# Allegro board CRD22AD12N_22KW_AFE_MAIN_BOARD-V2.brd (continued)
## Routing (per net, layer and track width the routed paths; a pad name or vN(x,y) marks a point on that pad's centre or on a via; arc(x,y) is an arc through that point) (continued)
GND_EARTH:
  vias: v1(48.26,79.38) v1(49.53,79.38) v1(49.53,58.42) v1(49.53,57.15) v1(49.53,55.88) v1(50.8,79.38) v1(68.58,46.99) v1(69.47,41.91) v1(69.47,40.64) v1(69.47,39.37) v1(69.85,46.99) v1(71.12,46.99) v1(83.13,69.85) v1(83.13,68.58) v1(83.13,67.31)
PGND: length 146.8
  TOP w0.762: v1(186.06,6.99) v1(184.78,6.99) 184.53,7.24 174.12,7.24 J2.5
  POWER03 w0.762: v1(271.78,15.24) v1(270.51,15.24) 227.08,15.24 222.63,10.79 220.09,10.79 216.85,7.56 214.95,7.56 211.84,4.45 188.59,4.45 v1(186.06,6.99)
  BOTTOM w0.381: R239.1 125.56,173.61 C23.2 ; C24.2 161.75,173.61 R227.1 ; R215.1 53.17,173.61 C27.2 ; R214.1 R236.1 197.95,173.61 C31.2 ; C28.2 91.44,172.13 92.92,173.61 R226.1
AC_LA: length 20.1
  BOTTOM w0.762: CL2_A1.6 128.91,72.53 R266.1 R28.1
AC_LA1: length 63.9
  POWER03 w2.54: RV2.1 186.32,30.86 213.74,30.86 222.53,39.65 RLY1.4
AC_LA_ADC: length 24.9
  TOP w0.152: v1(236.73,24.51) 239.9,21.34 239.9,4.7 J1.15
  BOTTOM w0.152: U4.12 v1(236.73,24.51)
AC_LA_OC: length 29.7
  TOP w0.152: v1(235.46,24.51) 235.46,10.16 J1.8
  BOTTOM w0.152: U4.13 v1(235.46,24.51) 235.71,24.51 237.87,22.35 237.87,20.09 237.21,19.43 R100.2
AC_LA_SAMP: length 117.2
  TOP w0.762: R146.1 52.83,11.56 v1(52.7,11.43)
  BOTTOM w0.762: v1(52.7,11.43) 54.48,13.21 82.17,13.21 83.52,14.55 83.52,20.14 86.74,23.37 113.16,23.37 116.59,26.8 116.59,36.96 111.38,42.16 111.38,52.58 R29.2
AC_LAB_G: length 30.1
  TOP w0.254: R155.1 R156.1 C171.2 57.53,20.32 57.66,20.19 C159.1 C160.1 60.83,20.19 61.09,20.45 67.31,20.45 C161.1 69.59,19.3 69.72,19.17 C164.1 C158.1 C157.1 74.42,20.45 76.46,20.45 D4.1 77.72,19.19 77.72,18.67 C166.2 78.74,17.66 U23.3
AC_LAB_SENSE: length 50
  TOP w0.254: D4.2 80.52,18.68 80.52,18.16 C166.1 v1(81.28,17.78) 81.28,17.53 80.01,16.25 U23.2 ; C167.1 C168.1 R153.2 50.67,17.14 50.67,16.51 R152.2 R146.2 50.67,12.7 50.67,12.19 v1(51.44,11.43)
  POWER03 w0.152: v1(81.28,17.78) 80.64,18.41 58.42,18.41 v1(51.44,11.43)
AC_LAB_SENSE_ADC: length 109.2
  POWER03 w0.152: v1(78.23,6.48) 79.06,5.65 83.12,5.65 84.58,7.11 107.19,7.11 111,3.3 159.38,3.3 161.29,1.4 175.9,1.4 J2.2
  BOTTOM w0.254: R154.2 C214.2 79.5,8.59 U24.1 78.93,8.57 78.23,7.87 v1(78.23,6.48)
AC_LB: length 38.8
  BOTTOM w0.762: CL2_A1.4 145.3,75.06 140.59,75.06 134.37,68.83 134.37,58.67 132.33,56.64 R37.1 R264.1
AC_LB_ADC: length 94.7
  TOP w0.152: J1.17 244.98,4.45 244.98,7.11 242.19,9.91 242.19,25.27 239.9,27.56 239.9,55.24 237.36,57.78 237.36,59.56 239.01,61.21 239.01,88.65 v1(236.73,90.93)
  BOTTOM w0.152: U5.12 v1(236.73,90.93)
AC_LB_OC: length 106
  TOP w0.152: v1(235.46,90.93) 237.87,88.52 237.87,61.34 234.44,57.91 234.44,51.18 236.98,48.64 236.98,27.43 234.44,24.89 234.44,11.05 230,6.6 230,5.08 230.63,4.45 232.28,4.45 J1.10
  BOTTOM w0.152: U5.13 v1(235.46,90.93) 236.47,89.92 236.73,89.92 237.87,88.77 237.87,86.51 237.21,85.85 R105.2
AC_LB_SAMP: length 81.9
  TOP w0.762: v1(88.27,11.43) 88.39,11.56 R163.1
  BOTTOM w0.762: R38.2 119.63,56.64 114.17,51.18 114.17,43.69 119.76,38.1 119.76,25.27 118.36,23.88 118.36,14.86 116.71,13.21 90.04,13.21 v1(88.27,11.43)
AC_LBC_G: length 29.7
  TOP w0.254: R175.1 R176.1 C193.2 94.1,20.32 C172.1 C173.1 102.75,20.32 C174.1 104.65,19.3 104.78,19.17 C177.1 C182.1 C181.1 109.6,20.7 111.77,20.7 D7.1 113.28,19.19 113.28,18.67 C180.2 114.3,17.66 U26.3
AC_LBC_SENSE: length 45
  TOP w0.254: C187.1 v1(85.72,19.05) ; C187.1 R170.2 85.85,16.76 85.85,16.13 R169.2 R163.2 ; C187.1 C186.1 ; D7.2 116.59,19.19 116.59,18.67 C180.1 115.69,16.64 v1(115.57,16.51) U26.2
  POWER03 w0.152: v1(115.57,16.51) 113.03,19.05 v1(85.72,19.05)
AC_LBC_SENSE_ADC: length 69.5
  POWER03 w0.152: v1(113.79,6.48) 116.46,3.81 159.6,3.81 161.6,1.8 173.76,1.8 J2.4
  BOTTOM w0.254: v1(113.79,6.48) 113.79,7.75 114.62,8.57 U27.1 115.06,8.59 C217.2 R164.2
AC_LC: length 28.8
  BOTTOM w0.762: CL2_A1.2 142.88,59.82 131.57,48.51 R45.1 R265.1
AC_LC1: length 94.7
  GND02 w2.54: RV5.1 176.93,19.94 202.31,19.94 204.85,22.48 204.85,40.89 218.31,54.36 218.31,63.86 RLY3.4
AC_LC_ADC: length 63.9
  TOP w0.152: J1.19 245.3,2.22 243.05,2.22 242.44,2.83 242.44,6.99 241.17,8.26 241.17,24.64 238.76,27.05 238.76,55.5 236.73,57.53 v1(236.73,57.91)
  BOTTOM w0.152: U6.12 v1(236.73,57.91)
AC_LC_OC: length 63.2
  TOP w0.152: J1.12 236.09,5.97 236.09,25.53 238,27.43 238,55.37 v1(235.46,57.91)
  BOTTOM w0.152: R108.2 237.21,52.83 237.87,53.49 237.87,55.75 236.73,56.9 236.47,56.9 v1(235.46,57.91) U6.13
AC_LC_SAMP: length 45.2
  TOP w0.762: v1(123.83,11.43) 123.95,11.56 R181.1
  BOTTOM w0.762: v1(123.83,11.43) 123.83,38.1 116.97,44.96 116.97,46.99 118.49,48.51 R46.2
AC_LCA_G: length 29.7
  TOP w0.254: R189.1 R190.1 C203.2 129.41,20.32 C198.1 C199.1 137.8,20.32 C190.1 139.57,19.3 139.7,19.17 C194.1 C189.1 C188.1 144.53,20.32 147.71,20.32 D10.1 148.84,19.19 148.84,18.67 C197.2 149.74,16.38 149.86,16.26 U30.3
AC_LCA_SENSE: length 45.8
  TOP w0.254: D10.2 152.27,19.31 152.27,18.8 C197.1 151.13,17.65 v1(151.13,16.51) U30.2 ; C202.1 v1(121.28,19.05) 121.16,18.92 R187.2 R181.2 ; C202.1 C201.1 ; C202.1 R188.2
  POWER03 w0.152: v1(151.13,16.51) 148.59,19.05 v1(121.28,19.05)
AC_LCA_SENSE_ADC: length 31.1
  POWER03 w0.152: v1(149.35,6.48) 151.51,4.32 159.81,4.32 161.9,2.22 171.64,2.22 J2.6
  BOTTOM w0.254: v1(149.35,6.48) 149.35,7.87 150.05,8.57 U31.1 150.6,9.89 C219.2 R179.2
CAN5V_GND: length 119.2
  POWER03 w0.152: J2.11 167.13,7.87 181.61,7.87 186.56,2.92 216.55,2.92 221.5,7.87 224.65,7.87 227.7,10.92 273.38,10.92 J5.2
CAN_5V: length 126.8
  POWER03 w0.152: J2.12 163.96,4.45 163.96,6.48 165.86,8.38 181.99,8.38 186.82,3.56 216.41,3.56 221.23,8.38 224.08,8.38 227.39,11.68 275.16,11.68 J5.1
CLAMPHA: length 17.4
  TOP w0.635: Q7.4 337.33,40 337.96,39.37 U17.7
  TOP w0.762: Q7.4 334.79,40.32 R69.2 332.49,43.81 R258.1
  BOTTOM w0.762: Q7.4 335.61,39.49 C7.1 R74.2
CLAMPHB: length 16.7
  TOP w0.635: U15.7 337.95,137.16 337.31,137.79 Q8.4
  TOP w0.762: R261.1 334.01,140.84 334.78,140.84 R70.2 334.79,138.11 Q8.4
  BOTTOM w0.762: Q8.4 335.61,137.28 C8.1 R75.2
CLAMPHC: length 16.7
  TOP w0.635: U19.7 337.96,88.27 337.33,88.9 Q9.4
  TOP w0.762: Q9.4 335.1,91.63 R71.2 334.78,91.95 R262.1
  BOTTOM w0.762: Q9.4 335.61,88.39 C9.1 R76.2
CLAMPLA: length 16.7
  TOP w0.635: U18.7 337.96,65.4 337.33,66.04 Q11.4
  TOP w0.762: R259.1 332.49,69.09 R86.2 334.79,66.36 Q11.4
  BOTTOM w0.762: Q11.4 335.61,65.53 C36.1 R91.2
CLAMPLB: length 16.7
  TOP w0.635: U16.7 338.2,163.19 337.57,163.83 Q10.4
  TOP w0.762: Q10.4 334.79,164.14 R82.2 332.49,166.88 R260.1
  BOTTOM w0.762: R87.2 C34.1 335.61,163.32 Q10.4
CLAMPLC: length 16.7
  TOP w0.635: Q12.4 337.69,114.93 338.33,114.3 U20.7
  TOP w0.762: R263.1 334.78,117.98 R85.2 334.79,115.25 Q12.4
  BOTTOM w0.762: R88.2 C35.1 335.61,114.42 Q12.4
GGND: length 309.8
  TOP w1.016: J4.6 301.68,2.74 302.39,2.03 309.37,2.03 318.77,11.43 347.85,11.43 360.28,23.86 U10.2
  GND02 w0.635: v1(215.26,10.29) 216.41,11.43 216.41,15.49 v1(215.26,16.64)
  POWER03 w0.508: J4.6 302.94,6.34 302.94,9.23 299.59,12.57 281.94,12.57 274.45,20.07 245.24,20.07 242.7,17.53 225.55,17.53 221.36,13.34 218.31,13.34 v1(215.26,10.29)
  BOTTOM w0.508: C2.1 R44.2 220.98,28.95 C1.2 ; C1.2 220.98,33.02 219.71,34.29 219.71,45.09 225.04,50.42 225.04,55.12 225.61,55.69 Q15.2 225.61,63.69 225.04,64.26 222.63,64.26 222.38,64.01 C213.2 ; C1.2 222.12,30.61 222.5,30.99 224.79,30.99 225.61,30.16 Q1.2 225.61,22.92 225.04,22.35 225.04,19.81 224.54,19.3 219.15,19.3 Q5.2 215.58,16.95 v1(215.26,16.64) 214.75,16.13 R66.1 212.6,16.13 212.09,16.64 U2.3 ; C213.2 220.98,66.17 220.09,67.06 220.09,80.52 225.17,85.6 225.17,89.28 225.61,89.72 Q4.2 225.61,96.59 224.92,97.28 221.23,97.28 C4.2 220.98,95.37 R62.2 C5.1 ; C213.2 220.85,63.88 R198.2 C212.1 ; Q2.2 215.58,10.6 v1(215.26,10.29) 214.75,9.78 R53.1 212.73,9.78 212.22,10.29 U1.3
  vias: v1(358.77,155.57) v1(358.77,153.03) v1(358.77,151.76) v1(358.77,129.54) v1(358.77,127) v1(358.77,125.73) v1(358.77,106.68) v1(358.77,104.14) v1(358.77,102.87) v1(358.77,80.64) v1(358.77,78.11) v1(358.77,76.83) v1(358.77,57.78) v1(358.77,55.24) v1(358.77,53.98) v1(358.77,31.75) v1(358.77,29.21) v1(358.77,27.94)
IOUT_ADC: length 344.6
  TOP w0.152: v1(19.05,97.79) 20.95,99.69 U3.12
  POWER03 w0.152: v1(153.67,2.54) 153.67,2.41 153.29,2.03 11.64,2.03 3.94,9.74 3.94,82.35 16.08,94.49 19.18,94.49 19.68,95 19.68,97.16 v1(19.05,97.79)
  BOTTOM w0.152: v1(153.67,2.54) 154.81,1.4 219.58,1.4 222,3.81 222,6.48 222.88,7.37 237.24,7.37 J1.14
LAB_G: length 13.3
  TOP w0.254: C171.1 R156.2 R155.2 55.12,16.89 55.51,16.5 D5.2 v1(54.15,15.88) R152.1 52.83,17.77 R153.1 C168.2 C167.2
  BOTTOM w0.152: R240.2 v1(54.15,15.88)
LBC_G: length 13.2
  TOP w0.254: C193.1 R176.2 R175.2 91.07,17.77 D9.2 v1(89.71,15.88) R169.1 88.39,17.77 R170.1 C187.2 C186.2
  BOTTOM w0.254: R241.2 v1(89.71,15.88)
LCA_G: length 13.8
  TOP w0.254: C201.2 C202.2 R188.1 123.95,17.77 R187.1 v1(125.27,15.88) D11.2 126.63,16.76 126.24,17.14 R189.2 R190.2 C203.1
  BOTTOM w0.254: R242.2 v1(125.27,15.88)
OUTPUT_OC: length 351
  TOP w0.152: R97.2 19.43,94.87 v1(19.05,95.25) 19.05,96.65 22.23,99.82 U3.13
  POWER03 w0.152: v1(19.05,95.25) 16.12,95.25 3.43,82.56 3.43,9.53 11.43,1.52 154.05,1.52 154.94,2.41 v1(154.94,2.54)
  BOTTOM w0.152: J1.16 239.14,8 222.63,8 221.49,6.86 221.49,4.32 219.07,1.91 155.57,1.91 v1(154.94,2.54)
PFC_G_HA: length 40.1
  TOP w0.762: Q7.3 337.96,37.46 339.87,35.56 C131.1 341.64,34.72 U10.6
  POWER03 w0.762: Q7.3 337.99,37.46 339.11,38.58 339.11,42.8 340.38,44.07 v1(342.78,44.07)
  BOTTOM w0.762: Q7.3 335.42,37.46 335.93,37.98 C7.2 R74.1 ; C130.2 342.91,44.19 v1(342.78,44.07)
PFC_G_HB: length 40.2
  TOP w0.762: U12.6 341.64,132.51 C117.1 339.24,133.35 337.33,135.25 Q8.3
  POWER03 w0.762: v1(342.78,141.86) 340.38,141.86 339.11,140.59 339.11,136.25 338.12,135.25 Q8.3
  BOTTOM w0.762: Q8.3 335.61,135.77 C8.2 R75.1 ; v1(342.78,141.86) 342.91,141.98 C116.2
PFC_G_HC: length 40.1
  TOP w0.762: Q9.3 337.95,86.36 339.85,84.45 C145.1 341.64,83.61 U14.6
  POWER03 w0.762: v1(342.78,92.96) 340.38,92.96 339.11,91.69 339.11,87.55 337.91,86.36 Q9.3
  BOTTOM w0.762: v1(342.78,92.96) 342.91,93.09 C144.2 ; R76.1 C9.2 335.61,86.87 Q9.3
PFC_G_LA: length 40.3
  TOP w0.762: Q11.3 337.33,63.5 339.24,61.59 C138.1 341.64,60.44 345.19,56.89 345.51,56.89 U9.6
  POWER03 w0.762: v1(342.78,70.1) 340.38,70.1 339.11,68.83 339.11,64.64 337.96,63.5 Q11.3
  BOTTOM w0.762: R91.1 C36.2 335.61,64.01 Q11.3 ; C137.2 342.91,70.23 v1(342.78,70.1)
PFC_G_LB: length 40.1
  TOP w0.762: U11.6 341.64,158.54 C124.1 339.24,159.38 337.33,161.29 Q10.3
  POWER03 w0.762: v1(342.78,167.89) 340.38,167.89 339.11,166.62 339.11,162.41 337.99,161.29 Q10.3
  BOTTOM w0.762: R87.1 C34.2 335.93,161.8 335.42,161.29 Q10.3 ; v1(342.78,167.89) 342.91,168.02 C123.2
PFC_G_LC: length 40.1
  TOP w0.762: U13.6 341.64,109.65 C152.1 340.12,110.49 338.22,112.39 Q12.3
  POWER03 w0.762: v1(342.78,119) 340.38,119 339.11,117.73 339.11,113.46 338.04,112.39 Q12.3
  BOTTOM w0.762: Q12.3 335.61,112.91 C35.2 R88.1 ; v1(342.78,119) 342.91,119.12 C151.2
PFCDRVHA: length 8.4
  TOP w0.635: U17.6 338.98,40.64 337.59,42.03 R69.1
  TOP w0.762: R69.1 338.84,45.07 D13.2
PFCDRVHB: length 7.8
  TOP w0.635: U15.6 338.71,138.43 337.59,139.55 R70.1
  TOP w0.762: D16.2 338.83,142.08 R70.1
PFCDRVHC: length 7.7
  TOP w0.635: R71.1 337.59,90.78 338.84,89.53 U19.6
  TOP w0.762: R71.1 338.95,93.32 D17.2
PFCDRVLA: length 7.9
  TOP w0.635: U18.6 338.58,66.67 337.59,67.67 R86.1
  TOP w0.762: R86.1 338.95,70.46 D14.2
PFCDRVLB: length 7.7
  TOP w0.635: U16.6 338.84,164.47 337.59,165.71 R82.1
  TOP w0.762: R82.1 338.95,168.25 D15.2
PFCDRVLC: length 7.8
  TOP w0.635: R85.1 337.59,116.69 338.71,115.57 U20.6
  TOP w0.762: R85.1 338.95,119.35 D18.2
PWM1A: length 165.3
  TOP w0.508: R126.1 v1(356.87,39.37)
  POWER03 w0.152: J1.1 225.41,1.41 231.66,1.41 232.56,2.31 232.56,3.99 233.12,4.55 257,4.55 259.22,2.32 339.38,2.32 356.46,19.41 356.46,38.96 v1(356.87,39.37)
PWM1B: length 191.3
  TOP w0.508: R130.1 v1(356.87,65.41)
  POWER03 w0.152: v1(356.87,65.41) 355.9,64.44 355.9,46.3 355.52,45.92 355.52,38.91 356.01,38.43 356.01,19.58 339.19,2.77 281.33,2.77 280.95,3.15 260.25,3.15 256.42,6.99 232.79,6.99 232.38,6.58 232.38,4.55 232.21,4.37 232.21,2.72 231.55,2.06 227.03,2.06 226.06,3.02 J1.3
PWM1C: length 262.4
  TOP w0.508: R118.1 v1(356.87,137.16)
  POWER03 w0.152: J1.5 227.33,4.57 227.33,6.86 228.98,8.51 257.05,8.51 260.88,4.67 280.95,4.67 281.94,3.68 338.58,3.68 354.74,19.84 354.74,32.74 352.98,34.49 352.98,46.05 354.81,47.88 354.81,59.94 354.33,60.43 354.33,70.15 354.79,70.61 354.79,82.73 354.33,83.19 354.33,95.12 355.6,96.39 355.6,135.89 v1(356.87,137.16)
PWM1D: length 286.1
  TOP w0.508: R122.1 v1(356.87,163.19)
  POWER03 w0.152: v1(356.87,163.19) 356.08,162.41 356.08,139.22 357.38,137.92 357.38,136.14 356.11,134.87 356.11,95.73 355.5,95.12 355.5,47.04 354.38,45.92 354.38,38.99 355.6,37.77 355.6,19.94 338.84,3.18 281.68,3.18 280.95,3.91 260.57,3.91 256.73,7.75 230.63,7.75 229.87,6.99 229.87,4.57 J1.7
PWM1E: length 202.9
  TOP w0.508: R134.1 v1(356.87,88.27)
  POWER03 w0.152: J1.9 235.57,1.41 339.86,1.41 357.89,19.43 357.89,87.25 v1(356.87,88.27)
PWM1F: length 225.6
  TOP w0.508: R138.1 v1(356.87,114.3)
  POWER03 w0.152: v1(356.87,114.3) 356.87,95.25 356.24,94.61 356.24,85.98 357.38,84.84 357.38,38.35 356.87,37.85 356.87,19.18 339.57,1.87 237.65,1.87 J1.11
RLYCTRL1: length 31.6
  TOP w0.152: v1(194.31,6.48) 195.96,4.83 219.2,4.83 220.22,5.84 J1.2
  BOTTOM w0.152: R58.2 193.16,6.48 v1(194.31,6.48)
RLYCTRL2: length 39
  TOP w0.152: v1(194.31,12.83) 193.8,12.32 193.8,10.16 197.87,6.1 211.2,6.1 212.09,6.99 224.92,6.99 J1.4
  BOTTOM w0.152: R67.2 194.19,12.7 v1(194.31,12.83)
VA+5V: length 35.4
  TOP w0.381: C159.2 C160.2 61.35,18.67 D3.2 v1(61.6,17.53) ; v1(75.82,16.51) 75.82,18.8 75.44,19.17 R142.1
  TOP w0.508: U21.3 54.22,11.19 v1(53.98,11.43)
  POWER03 w0.762: v1(53.98,11.43) 60.07,17.53 v1(61.6,17.53)
  BOTTOM w0.762: v1(61.6,17.53) 75.06,17.53 75.82,16.76 v1(75.82,16.51)
VB+5V: length 30.3
  TOP w0.381: C182.2 C181.2 R158.1 v1(109.47,16.51) ; D6.2 v1(97.29,17.78)
  TOP w0.508: U28.3 89.78,11.19 v1(89.53,11.43)
  POWER03 w0.762: v1(97.29,17.78) 96.77,17.78 92.96,13.97 92.08,13.97 v1(89.53,11.43)
  BOTTOM w0.762: v1(109.47,16.51) 108.2,17.78 v1(97.29,17.78)
VC+5V: length 47.6
  TOP w0.381: v1(132.6,17.65) D8.2 132.22,18.8 C199.2 C198.2 ; R171.1 145.67,19.17 146.05,18.8 v1(146.05,16.51)
  TOP w0.508: U32.3 125.34,11.19 v1(125.09,11.43)
  POWER03 w0.762: v1(146.05,16.51) 140.97,11.43 v1(125.09,11.43)
  BOTTOM w0.762: v1(132.6,17.65) 144.91,17.65 v1(146.05,16.51)
VO1+: length 33.6
  BOTTOM w0.381: R93.1 154.38,12.38 158.5,8.26 175.39,8.26 J2.1
VO2+: length 32.6
  BOTTOM w0.381: J2.3 173.61,7.49 158.24,7.49 153.36,12.38 153.36,18.43 R94.1
VP3.3D: length 407.4
  TOP w0.381: v1(26.04,93.98) 26.04,95.13 R95.1
  TOP w0.508: v1(152.02,6.48) 155.3,6.48 157.25,8.43 186.39,8.43 191.01,3.81 220.47,3.81 221.23,4.57 227.33,4.57 J1.6 228.6,7.62 233.17,12.19 233.17,17.27 v1(230.38,20.07) 232.92,22.61 232.92,25.4 235.46,27.94 235.46,48.39 v1(230.38,53.47) 233.17,56.26 233.17,58.42 236.85,62.1 236.85,80.01 v1(230.38,86.49)
  POWER03 w0.508: v1(152.02,6.48) 151.64,6.48 150.75,7.37 148.72,7.37 147.83,6.48 v1(116.46,6.48) 115.57,6.48 114.81,7.24 113.41,7.24 112.65,6.48 110.36,6.48 108.58,8.26 84.33,8.26 82.55,6.48 v1(80.9,6.48) 80.52,6.48 79.63,7.37 78.11,7.37 77.34,6.6 47.12,6.6 41.85,11.87 27.11,11.87 16.89,22.1 16.89,84.84 v1(26.04,93.98)
  BOTTOM w0.152: R106.1 v1(230.38,53.47) ; R103.1 v1(230.38,86.49) ; R98.1 v1(230.38,20.07)
  BOTTOM w0.381: v1(116.46,6.48) 116.84,6.86 R157.1 117.47,6.86 R159.1 ; v1(152.02,6.48) 152.4,6.86 R172.1 153.03,6.86 R174.1 ; R143.1 81.91,6.86 R141.1 81.28,6.86 v1(80.9,6.48)
VP+5V: length 488.7
  TOP w0.152: C111.1 356.75,134.62 R117.1 ; v1(194.31,7.75) 193.29,8.76 193.29,13.08 v1(194.31,14.1)
  TOP w0.381: U29.2 v1(146.69,7.62) ; v1(75.56,7.62) U22.2 ; U25.2 v1(111.12,7.62)
  TOP w0.508: v1(354.96,61.59) 355.09,61.72 R129.1 356.75,62.87 C132.1 ; v1(354.96,133.35) 355.09,133.47 R117.1 ; v1(354.96,84.45) 355.09,84.58 R133.1 356.75,85.72 C139.1 ; C125.1 356.75,36.83 R125.1 355.09,35.68 v1(354.96,35.56) ; v1(354.96,110.49) 355.09,110.61 R137.1 356.75,111.76 C146.1 ; C118.1 356.75,160.66 R121.1 355.09,159.51 v1(354.96,159.38)
  POWER03 w0.508: C55.1 244.32,16.51 226.57,16.51 222.12,12.07 219.46,12.07 216.09,8.7 213.55,8.7 210.57,5.71 196.34,5.71 v1(194.31,7.75) 192.28,9.78 148.84,9.78 v1(146.69,7.62) 120.02,7.62 117.98,9.65 113.16,9.65 v1(111.12,7.62) 108.84,9.91 77.85,9.91 v1(75.56,7.62)
  BOTTOM w0.152: v1(194.31,14.1) R65.2 C6.1 ; v1(194.31,7.75) R52.2 C3.1
  BOTTOM w0.381: v1(111.12,7.62) 110.74,7.24 C169.2 C170.2 ; v1(75.56,7.62) 75.18,7.24 C156.2 C155.2 ; v1(146.69,7.62) 146.3,7.24 C183.2 C184.2
  BOTTOM w0.508: v1(354.96,159.38) 354.96,148.21 357.76,145.41 357.76,136.14 v1(354.96,133.35) 354.96,123.57 357.89,120.65 357.89,113.41 v1(354.96,110.49) 354.96,95.38 357.89,92.46 357.89,87.38 v1(354.96,84.45) 354.96,72.77 357.76,69.98 357.76,64.39 v1(354.96,61.59) 354.96,49.66 357.89,46.74 357.89,38.48 v1(354.96,35.56) 354.96,16.13 341.5,2.67 257.3,2.67
VP+15V: length 252.6
  TOP w1.016: 361.31,38.1 356.11,32.89 356.11,23.24 345.95,13.08 307.14,13.08 J4.5
  GND02 w0.635: v1(215.27,5.84) 214.25,6.86 214.25,11.18 v1(215.27,12.19)
  POWER03 w1.016: v1(215.01,65.53) 218.95,61.59 218.95,57.4 231.9,44.45 231.9,33.66 227.58,29.34 219.46,29.34 216.28,26.16 216.28,13.21 v1(215.27,12.19) ; J4.5 298.63,10.67 279.91,10.67 276.99,13.59 227.46,13.59 223.27,9.4 220.6,9.4 217.04,5.84 v1(215.27,5.84)
  BOTTOM w0.508: R191.1 v1(215.01,65.53) ; R57.1 v1(215.27,12.19) ; R36.1 v1(215.27,5.84)
  vias: v1(361.31,160.66) v1(361.31,134.62) v1(361.31,111.76) v1(361.31,85.72) v1(361.31,62.87) v1(361.31,36.83) v1(363.86,134.62) v1(363.86,111.76) v1(363.86,85.72) v1(363.86,62.87) v1(363.86,36.83)
VPFC: length 44.5
  BOTTOM w0.381: C11.1 143.97,128.27 R232.2 ; C10.1 107.78,128.27 R220.2 ; R207.2 216.36,128.9 C16.1 ; R218.2 71.58,128.27 C17.1 ; R206.2 R229.2 180.17,128.9 C13.1
  vias: v1(70.48,123.19) v1(70.48,121.92) v1(72.39,123.19) v1(72.39,121.92) v1(74.3,123.19) v1(74.3,121.92) v1(76.2,123.19) v1(76.2,121.92) v1(216.53,123.83) v1(216.53,122.56) v1(218.44,123.83) v1(218.44,122.56) v1(220.34,123.83) v1(220.34,122.56) v1(222.25,123.83) v1(222.25,122.56)
VS+5V: length 93.5
  POWER03 w0.508: J2.7 171.58,7.24 181.1,7.24 186.06,2.29 217.17,2.29 222.12,7.24 224.92,7.24 227.84,10.16 v1(255.27,10.16) v1(256.54,10.16) v1(257.81,10.16)
N17200031: length 4.5
  TOP w0.254: C165.1 R147.2 58.42,11.43 58.81,11.04 U21.1
N17200043: length 6.9
  TOP w0.254: R149.1 R148.1 R150.1 R147.1 C165.2 59.69,14.86 59.81,14.98 D5.1
N17200052: length 12.2
  TOP w0.508: R149.2 R148.2 R150.2 57.15,11.43 56.52,10.79 U21.2 U21.4
N17202885: length 4.5
  TOP w0.254: U28.1 94.37,11.04 93.98,11.43 R165.2 C185.1
N17202901: length 6.9
  TOP w0.254: R167.1 R166.1 R168.1 R165.1 C185.2 95.37,14.21 D9.1
N17202907: length 12.2
  TOP w0.508: R167.2 R166.2 R168.2 92.71,11.43 92.08,10.79 U28.2 U28.4
N17203702: length 4.5
  TOP w0.254: C200.1 R183.2 129.54,11.43 129.93,11.04 U32.1
N17203726: length 12.2
  TOP w0.508: R185.2 R184.2 R186.2 128.27,11.43 127.64,10.79 U32.2 U32.4
N17203738: length 6.9
  TOP w0.254: R185.1 R184.1 R186.1 R183.1 C200.2 130.93,14.21 D11.1
N17207655: length 13.1
  TOP w0.381: C158.2 C157.2 R142.2 v1(74.55,16.51) ; U23.1 v1(81.28,16.51)
  BOTTOM w0.381: v1(74.55,16.51) 75.56,15.49 80.26,15.49 v1(81.28,16.51)
N17208388: length 5.6
  TOP w0.254: U23.8 v1(81.28,2.54)
  BOTTOM w0.254: C162.1 C163.1 R143.2 81.91,3.18 v1(81.28,2.54)
N17208484: length 3
  TOP w0.254: U23.7 v1(80.01,2.54)
  BOTTOM w0.254: R145.1 80.65,3.18 v1(80.01,2.54)
N17208491: length 5.4
  TOP w0.254: U23.6 v1(78.74,2.54)
  BOTTOM w0.254: R151.1 76.84,2.16 77.09,1.91 78.1,1.91 v1(78.74,2.54)
N17208678: length 8.5
  BOTTOM w0.254: R151.2 76.84,5.84 76.98,5.99 U24.4 76.98,7.22 75.82,8.38 75.82,9.53 76.2,9.91 C214.1 R154.1
N17208781: length 7.9
  POWER03 w0.254: v1(78.23,8.89) 80.52,8.89 v1(80.77,8.64)
  BOTTOM w0.254: C154.1 C153.1 R141.2 81.03,8.38 v1(80.77,8.64) ; U24.5 77.98,8.57 78.23,8.82 v1(78.23,8.89)
N17209770: length 32.7
  TOP w0.381: U26.1 v1(116.84,16.51) ; C172.2 C173.2 v1(95.38,17.65) ; v1(110.74,16.51) 110.74,18.8 110.37,19.17 R158.2
  POWER03 w0.762: v1(116.84,16.51) 115.57,15.24 112.01,15.24 v1(110.74,16.51)
  BOTTOM w0.762: v1(95.38,17.65) 97.03,19.3 108.97,19.3 110.74,17.53 v1(110.74,16.51)
N17209888: length 5.6
  TOP w0.254: U26.8 v1(116.84,2.54)
  BOTTOM w0.254: C178.1 C179.1 R159.2 117.47,3.18 v1(116.84,2.54)
N17209896: length 3
  TOP w0.254: U26.7 v1(115.57,2.54)
  BOTTOM w0.254: v1(115.57,2.54) 116.21,3.18 R161.1
N17209898: length 5.4
  TOP w0.254: U26.6 v1(114.3,2.54)
  BOTTOM w0.254: R162.1 112.4,3.68 112.4,2.16 112.65,1.91 113.66,1.91 v1(114.3,2.54)
N17209922: length 4
  BOTTOM w0.254: U27.3 115.04,6.08 114.93,5.97 114.93,5.2 ; R161.2 C216.1 114.93,5.2 ; 114.93,5.2 R160.1
N17209924: length 8.2
  BOTTOM w0.254: R164.1 C217.1 112.14,9.91 111.38,9.14 111.38,8.38 112.54,7.22 U27.4 112.54,6.12 112.39,5.97 R162.2
N17209942: length 7.7
  POWER03 w0.254: v1(113.79,8.76) 113.92,8.63 116.33,8.63 v1(116.33,8.64)
  BOTTOM w0.254: v1(116.33,8.64) 116.59,8.38 R157.2 C175.1 C176.1 ; v1(113.79,8.76) 113.6,8.57 U27.5
N17210692: length 13.8
  TOP w0.381: U30.1 v1(152.4,16.51) ; C189.2 C188.2 R171.2 v1(144.78,16.51)
  BOTTOM w0.381: v1(144.78,16.51) 145.67,15.62 151.51,15.62 v1(152.4,16.51)
N17210810: length 5.6
  TOP w0.254: v1(152.4,2.54) U30.8
  BOTTOM w0.254: v1(152.4,2.54) 153.03,3.18 R174.2 C196.1 C195.1
N17210816: length 3
  TOP w0.254: v1(151.13,2.54) U30.7
  BOTTOM w0.254: R177.1 151.77,3.18 v1(151.13,2.54)
N17210820: length 5.4
  TOP w0.254: v1(149.86,2.54) U30.6
  BOTTOM w0.254: R178.1 147.96,2.16 148.21,1.91 149.22,1.91 v1(149.86,2.54)
N17210844: length 4
  BOTTOM w0.254: R173.1 150.49,5.59 150.6,5.69 U31.3 ; R173.1 R177.2 ; R173.1 C218.1
N17210846: length 8.3
  BOTTOM w0.254: R178.2 147.95,5.21 147.95,5.71 148.1,5.86 U31.4 148.1,7.22 146.94,8.38 146.94,9.27 147.57,9.91 C219.1 R179.1
N17210864: length 7.8
  POWER03 w0.254: v1(149.35,8.89) 149.61,8.63 151.89,8.63 v1(151.89,8.64)
  BOTTOM w0.254: C192.1 C191.1 R172.2 152.15,8.38 v1(151.89,8.64) ; U31.5 149.03,8.57 v1(149.35,8.89)
N17217934: length 4
  BOTTOM w0.254: C215.1 R144.1 ; R144.1 79.37,6.56 U24.3 ; R144.1 R145.2
N17223082: length 14.2
  TOP w0.254: C164.2 69.6,17.66 69.47,17.53 C161.2 67.3,17.53 D3.1 62.1,15.12 62.1,12.83 62.23,12.7 U22.4
N17223482: length 14
  TOP w0.254: U25.4 97.79,12.7 97.66,12.83 97.66,15.25 D6.1 103.24,17.53 C174.2 104.52,17.53 104.65,17.66 C177.2
N17224001: length 13.9
  TOP w0.254: C194.2 140.59,17.53 C190.2 138.55,17.53 D8.1 133.22,15.5 133.22,12.83 133.35,12.7 U29.4
N17746491: length 5.2
  TOP w0.508: C126.1 C127.1 ; C127.1 R125.2 ; C127.1 U17.1
N17747250: length 10.8
  TOP w0.508: R126.2 v1(356.87,43.18) ; v1(353.69,43.18) 353.57,43.06 R127.1 C128.1 353.52,40.59 353.19,40.59 351.97,39.37 U17.2
  BOTTOM w0.508: v1(353.69,43.18) 354.46,42.42 356.11,42.42 v1(356.87,43.18)
N17751858: length 2.9
  TOP w0.508: v1(342.78,42.85) 342.71,42.85 341.77,41.91 U17.5
N17896717: length 2.2
  BOTTOM w0.762: R29.1 R28.2
N17896948: length 9.5
  BOTTOM w0.381: R25.1 XC7.2 ; R7.1 XC1.2
N17897141: length 2.3
  BOTTOM w0.381: R22.2 R19.1
N17897143: length 2.3
  BOTTOM w0.381: R25.2 R22.1
N17903019: length 2.3
  BOTTOM w0.381: R10.1 R13.2
N17903021: length 2.3
  BOTTOM w0.381: R13.1 R16.2
N17903179: length 2.3
  BOTTOM w0.381: R4.2 R1.1
N17903181: length 2.3
  BOTTOM w0.381: R7.2 R4.1
N17908018: length 4.6
  BOTTOM w0.508: XC5.1 110.01,105.23 R11.2
N17908020: length 5.3
  BOTTOM w0.381: R26.1 XC8.2 110.8,33.78
N17908040: length 2.3
  BOTTOM w0.381: R11.1 R14.2
N17908042: length 2.3
  BOTTOM w0.381: R14.1 R17.2
N17908092: length 2.3
  BOTTOM w0.381: R2.1 R5.2
N17908094: length 2.3
  BOTTOM w0.381: R8.2 R5.1
N17908164: length 2.3
  BOTTOM w0.381: R23.2 R20.1
N17908166: length 2.3
  BOTTOM w0.381: R26.2 R23.1
N17911015: length 7.4
  BOTTOM w0.508: Q1.1 223.71,29.02 222,27.31 R44.1 C2.2 219.58,27.31 219.58,25.65 R50.1
N17911017: length 27.1
  POWER03 w0.152: v1(222.25,16.51) 221.62,15.88 219.84,15.88 218.31,17.4 218.31,21.72 v1(222.12,25.53)
  BOTTOM w0.152: R43.1 219.71,7.87 218.81,8.77 Q2.3 219.38,9.65 219.96,10.24 219.96,11.05 220.6,11.68 220.6,14.86 v1(222.25,16.51)
  BOTTOM w0.508: R50.2 220.98,25.53 v1(222.12,25.53)
N17911032: length 7.1
  BOTTOM w0.508: R42.2 223.52,22.23 223.71,22.41 RLY1.2 223.71,25.46 224.66,26.42 224.66,27.69 Q1.3
N17911094: length 40
  POWER03 w0.152: v1(218.31,25.53) 217.68,24.89 217.68,17.14 219.46,15.37 222.25,15.37 v1(223.39,16.51)
  BOTTOM w0.152: R51.2 R36.2 218.69,5.84 218.82,5.72 R43.2 220.47,5.72 220.85,6.1 220.85,10.92 221.23,11.3 221.23,14.35 v1(223.39,16.51)
  BOTTOM w0.508: C1.1 218.95,31.11 217.93,31.11 217.17,30.35 R35.2 217.55,30.1 218.57,29.08 218.57,25.78 v1(218.31,25.53)
N17911109: length 6.6
  BOTTOM w0.508: D1.2 213.62,24.28 RLY1.1 212.6,25.31 R33.1
N17911126: length 2.3
  BOTTOM w0.508: R34.2 R35.1
N17911128: length 2.3
  BOTTOM w0.508: R33.2 R34.1
N17911225: length 7.4
  BOTTOM w0.508: Q4.1 223.71,95.44 222,93.73 R62.1 C5.2 219.58,92.07 R63.1
N17911227: length 94
  POWER03 w0.152: v1(222.12,91.95) 221.62,91.44 221.62,59.44 v1(222.12,58.93) 221.62,58.42 221.62,57.15 233.93,44.83 233.93,30.73 220.98,17.78 v1(220.98,16.51)
  BOTTOM w0.152: R61.1 219.71,14.1 218.81,14.99 Q5.3 220.47,16 v1(220.98,16.51)
  BOTTOM w0.508: R201.2 v1(222.12,58.93) ; R63.2 v1(222.12,91.95)
N17911239: length 7.1
  BOTTOM w0.508: Q4.3 223.71,93.16 RLY2.2 223.71,90.19 223.52,90 R60.2
N17911299: length 103.9
  POWER03 w0.152: v1(219.58,98.3) 220.85,97.03 220.85,57.15 233.17,44.83 233.17,30.99 219.96,17.78 v1(219.07,17.78)
  BOTTOM w0.152: v1(219.07,17.78) 217.68,16.38 217.68,15.62 217.93,15.37 R64.2 R57.2 219.59,12.19 R61.2
  BOTTOM w0.508: R56.2 218.95,96.52 C4.1 219.46,98.17 v1(219.58,98.3)
N17911323: length 6.6
  BOTTOM w0.508: D2.2 213.62,90.7 RLY2.1 212.6,91.73 R54.1
N17911339: length 2.5
  BOTTOM w0.508: R56.1 R55.2
N17911341: length 2.5
  BOTTOM w0.508: R54.2 R55.1
N17913837: length 2.2
  BOTTOM w0.762: R38.1 R37.2
N17913950: length 2.2
  BOTTOM w0.762: R45.2 R46.1
N17916039: length 162.3
  BOTTOM w1.016: F7.1 238.14,121.18 234.57,117.6 211.07,117.6 207.14,121.54 162.05,121.54 155.7,115.19 155.7,86.74 160.4,82.04 160.4,57.4 156.1,53.11 R73.2 R72.2
N17916612: length 2.3
  BOTTOM w0.381: R72.1 R78.2
N17916616: length 2.3
  BOTTOM w0.381: R78.1 R80.2
N17916654: length 2.3
  BOTTOM w0.381: R77.1 R79.2
N17916656: length 2.3
  BOTTOM w0.381: R79.1 R81.2
N17919278: length 2.3
  BOTTOM w0.381: R83.1 R89.2
N17919280: length 2.3
  BOTTOM w0.381: R89.1 R92.2
N17919331: length 2.3
  BOTTOM w0.381: R84.1 R90.2
N17919333: length 2.3
  BOTTOM w0.381: R90.1 R93.2
N17919338: length 2.3
  BOTTOM w0.381: R80.1 R83.2
N17919341: length 2.3
  BOTTOM w0.381: R81.1 R84.2
N17920487: length 78
  BOTTOM w0.381: C13.2 180.17,141.86 R230.1 R208.1 ; R210.2 R234.2 197.95,160.65 C31.1 ; R233.1 143.97,141.23 C11.2 ; R223.2 161.75,160.65 C24.1 ; C10.2 107.78,141.23 R221.1 ; R219.1 71.58,141.23 C17.2 ; R222.2 90.68,160.65 ; R237.2 125.56,160.65 C23.1 ; R211.2 53.17,160.65 C27.1 ; 218.9,141.86 R209.1
N17922701: length 5.2
  TOP w0.508: R117.2 C113.1 ; C113.1 C112.1 ; C113.1 U15.1
N17922735: length 10.8
  TOP w0.508: R118.2 v1(356.87,140.97) ; U15.2 351.92,137.16 353.14,138.38 353.52,138.38 C114.1 R119.1 353.57,140.85 v1(353.69,140.97)
  BOTTOM w0.508: v1(353.69,140.97) 354.46,140.21 356.11,140.21 v1(356.87,140.97)
N17922803: length 2.9
  TOP w0.508: v1(342.78,140.64) 341.84,139.7 U15.5
N17923309: length 5.2
  TOP w0.508: C119.1 C120.1 ; C120.1 U16.1 ; C120.1 R121.2
N17923353: length 10.8
  TOP w0.508: R122.2 v1(356.87,167) ; U16.2 351.92,163.19 353.14,164.41 353.52,164.41 C121.1 R123.1 353.57,166.88 v1(353.69,167)
  BOTTOM w0.508: v1(356.87,167) 356.11,166.24 354.46,166.24 v1(353.69,167)
N17923421: length 2.9
  TOP w0.508: U16.5 341.84,165.74 v1(342.78,166.67)
N17924447: length 5.2
  TOP w0.508: U18.1 C134.1 ; C134.1 C133.1 ; C134.1 R129.2
N17924481: length 10.8
  TOP w0.508: v1(353.69,69.22) 353.57,69.09 R131.1 C135.1 353.52,66.62 353.21,66.62 351.99,65.41 U18.2 ; R130.2 v1(356.87,69.22)
  BOTTOM w0.508: v1(356.87,69.22) 356.11,68.45 354.46,68.45 v1(353.69,69.22)
N17924549: length 2.9
  TOP w0.508: 340.28,67.94 341.84,67.94 v1(342.78,68.88)
N17925295: length 5.2
  TOP w0.508: R133.2 353.57,85.73 C141.1 ; C141.1 U19.1 ; C141.1 C140.1
N17925329: length 10.8
  TOP w0.508: v1(353.69,92.08) 353.57,91.95 R136.1 C142.1 352.81,89.53 351.54,88.27 U19.2 ; R134.2 v1(356.87,92.08)
  BOTTOM w0.508: v1(353.69,92.08) 354.46,91.31 356.11,91.31 v1(356.87,92.08)
N17925397: length 2.9
  TOP w0.508: v1(342.78,91.74) 341.84,90.81 U19.5
N17925494: length 5.2
  TOP w0.508: C148.1 C147.1 ; C148.1 U20.1 ; C148.1 R137.2
N17925544: length 10.8
  TOP w0.508: R138.2 v1(356.87,118.11) ; v1(353.69,118.11) 353.57,117.99 R139.1 C149.1 353.44,115.44 352.94,115.44 351.79,114.3 U20.2
  BOTTOM w0.508: v1(353.69,118.11) 354.46,117.35 356.11,117.35 v1(356.87,118.11)
N17925612: length 2.9
  TOP w0.508: U20.5 341.84,116.84 v1(342.78,117.78)
N17951662: length 10.1
  BOTTOM w0.381: R99.1 234.7,21.09 R100.1 233.55,19.43 233.04,19.94 R98.2 C39.1 C40.1 232.92,22.73 U4.15
N17951990: length 5.1
  BOTTOM w0.152: U4.14 234.19,24.64 234.82,24 R99.2 R102.1
N17952680: length 10.1
  BOTTOM w0.381: U5.15 232.92,90.42 233.04,90.3 C42.1 C41.1 R103.2 233.04,86.36 233.55,85.85 R105.1 234.7,87.51 R104.1
N17952780: length 5.1
  BOTTOM w0.152: R109.1 R104.2 234.82,90.42 234.19,91.06 U5.14
N17953229: length 10.1
  BOTTOM w0.381: R107.1 234.7,54.49 R108.1 233.55,52.83 233.04,53.34 R106.2 C43.1 C44.1 232.92,56.13 U6.15
N17953329: length 5.1
  BOTTOM w0.152: U6.14 234.19,58.04 234.82,57.4 R107.2 R110.1
N17988040: length 4.5
  BOTTOM w0.152: R67.1 R68.2 194.56,15.88 194.75,15.69 Q6.1
N17988101: length 2.9
  BOTTOM w0.152: U2.2 197.86,16.64 Q6.3
N17988123: length 8.2
  BOTTOM w0.152: U2.4 212.34,14.1 212.85,14.61 R66.2 215.14,14.61 215.59,15.05 Q5.1 216.8,14.36 216.41,13.97 R64.1
N17988189: length 3.1
  BOTTOM w0.152: U2.1 R65.1
N17989219: length 4.5
  BOTTOM w0.152: R58.1 R59.2 194.63,9.53 194.82,9.34 Q3.1
N17989262: length 2.9
  BOTTOM w0.152: U1.2 Q3.3
N17989280: length 8.2
  BOTTOM w0.152: R51.1 216.41,7.75 216.8,8.13 Q2.1 215.33,8.7 214.89,8.26 R53.2 212.98,8.26 212.47,7.75 U1.4
N17989337: length 3.1
  BOTTOM w0.152: U1.1 R52.1
N17992674: length 2.3
  BOTTOM w0.381: R73.1 R77.2
N17992702: length 2.3
  BOTTOM w0.381: R92.1 R94.2
N18031729: length 14.2
  TOP w0.381: U3.16 26.04,103 25.78,103.25 25.02,103.25 24.77,103 U3.15 24.77,99.19 24.64,99.06 24.64,97.79 C38.1 C37.1 R95.2 24.64,95.12 24.39,94.87 R97.1 23.11,95.38 22.86,95.63 R96.1
N18031813: length 5.1
  TOP w0.152: R101.1 R96.2 23.5,98.55 U3.14
N18077527: length 4
  BOTTOM w0.508: C213.1 218.95,63.5 R200.2 217.68,63.51 R191.2
N18077715: length 7.4
  BOTTOM w0.508: Q15.1 223.71,62.42 222,60.71 R198.1 C212.2 219.58,59.05 R201.1
N18077724: length 7.1
  BOTTOM w0.508: Q15.3 223.71,60.14 RLY3.2 223.71,57.17 223.52,56.98 R203.2
N18077784: length 6.6
  BOTTOM w0.508: R199.1 212.6,58.71 RLY3.1 213.62,57.68 D12.2
N18077797: length 2.5
  BOTTOM w0.508: R200.1 R202.2
N18077799: length 2.5
  BOTTOM w0.508: R199.2 R202.1
N18083752: length 2.3
  BOTTOM w0.381: R204.2 R206.1
N18083755: length 2.3
  BOTTOM w0.381: R205.2 R207.1
N18083758: length 2.3
  BOTTOM w0.381: R208.2 R204.1
N18083761: length 2.3
  BOTTOM w0.381: R209.2 R205.1
N18084124: length 2.3
  BOTTOM w0.381: R212.2 R210.1
N18084127: length 2.3
  BOTTOM w0.381: R213.2 R211.1
N18084130: length 2.3
  BOTTOM w0.381: R215.2 R213.1
N18084133: length 2.3
  BOTTOM w0.381: R214.2 R212.1
N18084369: length 2.3
  BOTTOM w0.381: R218.1 R216.2
N18084371: length 2.3
  BOTTOM w0.381: R220.1 R217.2
N18084373: length 2.3
  BOTTOM w0.381: R216.1 R219.2
N18084375: length 2.3
  BOTTOM w0.381: R217.1 R221.2
N18084659: length 2.3
  BOTTOM w0.381: R222.1 R225.2
N18084661: length 2.3
  BOTTOM w0.381: R224.2 R223.1
N18084679: length 2.3
  BOTTOM w0.381: R227.2 R224.1
N18084681: length 2.3
  BOTTOM w0.381: R225.1 R226.2
N18089484: length 2.3
  BOTTOM w0.381: R229.1 R228.2
N18089486: length 2.3
  BOTTOM w0.381: R228.1 R230.2
N18089654: length 2.3
  BOTTOM w0.381: R232.1 R231.2
N18089656: length 2.3
  BOTTOM w0.508: R233.2 R231.1
N18089831: length 2.3
  BOTTOM w0.381: R234.1 R235.2
N18089841: length 2.3
  BOTTOM w0.381: R235.1 R236.2
N18090018: length 2.3
  BOTTOM w0.381: R237.1 R238.2
N18090028: length 2.3
  BOTTOM w0.381: R238.1 R239.2
N18151288: length 59.3
  POWER03 w0.762: v1(96.77,15.88) 99.44,13.21 116.71,13.21 118.36,14.86 118.36,23.88 119.76,25.27 v1(119.76,46.1)
  BOTTOM w0.762: v1(119.76,46.1) R244.2 ; R241.1 v1(96.77,15.88)
N18151343: length 106.4
  POWER03 w0.762: v1(119.76,54.23) 113.03,54.23 111.38,52.58 111.38,42.16 116.59,36.96 116.59,26.8 113.16,23.37 86.74,23.37 83.52,20.14 83.52,14.55 82.17,13.21 63.75,13.21 v1(61.09,15.88)
  BOTTOM w0.762: v1(119.76,54.23) R243.2 ; R240.1 v1(61.09,15.88)
N18151366: length 70.1
  POWER03 w0.762: v1(119.76,64.77) 123.83,60.71 123.83,25.02 120.14,21.34 120.14,15.11 121.54,13.72 130.18,13.72 v1(132.33,15.88)
  BOTTOM w0.762: v1(119.76,64.77) R245.2 ; R242.1 v1(132.33,15.88)
N18156742: length 68.6
  BOTTOM w0.635: XC12.2 XC3.2 182.63,56.01 183.64,57.02 R9.1 ; R18.1 183.89,84.96 182.63,83.69 XC6.2 XC11.2 ; XC10.2 XC9.2 182.63,27.43 183.64,28.45 R27.1
N18156744: length 2.3
  BOTTOM w0.381: R12.1 R15.2
N18156746: length 2.3
  BOTTOM w0.381: R15.1 R18.2
N18156778: length 2.3
  BOTTOM w0.381: R3.1 R6.2
N18156780: length 2.3
  BOTTOM w0.381: R6.1 R9.2
N18156832: length 2.3
  BOTTOM w0.381: R21.1 R24.2
N18156834: length 2.3
  BOTTOM w0.381: R24.1 R27.2
N18179724: length 2.1
  TOP w0.762: D13.1 332.49,46.61 R258.2
N18179852: length 2.2
  TOP w0.762: R259.2 334.65,71.88 D14.1
N18179938: length 2.2
  TOP w0.762: R260.2 334.65,169.67 D15.1
N18180027: length 2
  TOP w0.762: R261.2 334.52,143.64 D16.1
N18180134: length 2.2
  TOP w0.762: R262.2 334.65,94.74 D17.1
N18180239: length 2.2
  TOP w0.762: R263.2 334.65,120.78 D18.1
N18184240: length 2.2
  BOTTOM w0.762: R264.2 R243.1
N18184278: length 2.2
  BOTTOM w0.762: R265.2 R244.1
N18184299: length 2.2
  BOTTOM w0.762: R266.2 R245.1
N179111791: length 7.6
  BOTTOM w1.778: RV1.1 168.81,34.37 RV2.2
N179111870: length 2.8
  BOTTOM w0.508: D1.1 R42.1
N179113920: length 2.8
  BOTTOM w0.508: D2.1 217.92,87.5 R60.1
N180778471: length 7.6
  BOTTOM w1.778: RV6.1 RV5.2
N180778550: length 2.8
  BOTTOM w0.508: D12.1 217.92,54.48 R203.1

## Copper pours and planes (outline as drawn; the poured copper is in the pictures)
-3V_PFCHA on BOTTOM (solid shape): 353.69,32 353.69,25.65 353.44,25.4 352.17,25.4 351.92,25.65 351.92,29.21 352.17,29.46 352.17,30.48 351.66,30.99 351.66,32.13 351.79,32.26 353.44,32.26
-3V_PFCHB on BOTTOM (solid shape): 353.69,129.79 353.69,123.44 353.44,123.19 352.17,123.19 351.92,123.44 351.92,127 352.17,127.25 352.17,128.27 351.66,128.78 351.66,129.92 351.79,130.05 353.44,130.05
-3V_PFCHC on BOTTOM (solid shape): 353.69,81.03 353.69,74.55 353.44,74.3 352.17,74.3 351.92,74.55 351.92,78.11 352.17,78.36 352.17,79.38 351.66,79.88 351.66,81.03 351.79,81.15 353.57,81.15
-3V_PFCLA on BOTTOM (solid shape): 353.69,58.17 353.69,51.69 353.44,51.44 352.17,51.44 351.92,51.69 351.92,55.24 352.17,55.5 352.17,56.52 351.66,57.02 351.66,58.17 351.79,58.29 353.57,58.29
-3V_PFCLB on BOTTOM (solid shape): 353.69,155.83 353.69,149.48 353.44,149.22 352.17,149.22 351.92,149.48 351.92,153.03 352.17,153.29 352.17,154.31 351.66,154.81 351.66,155.96 351.79,156.08 353.44,156.08
-3V_PFCLC on BOTTOM (solid shape): 353.69,107.06 353.69,100.58 353.44,100.33 352.17,100.33 351.92,100.58 351.92,104.14 352.17,104.39 352.17,105.41 351.66,105.92 351.66,107.06 351.79,107.19 353.57,107.19
AGND on TOP (solid shape): 355.6,167.97 355.6,162.69 355.85,162.43 357.12,162.43 357.25,162.31 357.25,161.54 357.2,161.49 354.84,161.49 354.71,161.62 354.71,166.7 354.69,166.73 354.69,166.9 353.95,167.64 352.81,167.64 351.92,166.75 351.92,164.54 351.54,164.16 350.27,164.16 350.14,164.29 350.14,168.1 350.52,168.48 355.09,168.48
AGND on TOP (solid shape): 355.6,141.94 355.6,136.65 355.85,136.4 357.12,136.4 357.25,136.27 357.25,135.51 357.2,135.46 354.84,135.46 354.71,135.59 354.71,140.67 354.69,140.69 354.69,140.87 353.95,141.6 352.81,141.6 351.92,140.72 351.92,138.51 351.54,138.13 350.27,138.13 350.14,138.25 350.14,142.06 350.52,142.44 355.09,142.44
AGND on TOP (solid shape): 355.6,119.08 355.6,113.79 355.85,113.54 357.12,113.54 357.25,113.41 357.25,112.65 357.2,112.6 354.84,112.6 354.71,112.73 354.71,117.81 354.69,117.83 354.69,118.01 353.95,118.75 352.81,118.75 351.92,117.86 351.92,115.65 351.54,115.27 350.27,115.27 350.14,115.39 350.14,119.2 350.52,119.58 355.09,119.58
AGND on TOP (solid shape): 355.6,93.04 355.6,87.76 355.85,87.5 357.12,87.5 357.25,87.38 357.25,86.61 357.2,86.56 354.84,86.56 354.71,86.69 354.71,91.77 354.69,91.8 354.69,91.97 353.95,92.71 352.81,92.71 351.92,91.82 351.92,89.61 351.54,89.23 350.27,89.23 350.14,89.36 350.14,93.17 350.52,93.55 355.09,93.55
AGND on TOP (solid shape): 355.6,70.18 355.6,64.9 355.85,64.64 357.12,64.64 357.25,64.52 357.25,63.75 357.2,63.7 354.84,63.7 354.71,63.83 354.71,68.91 354.69,68.94 354.69,69.11 353.95,69.85 352.81,69.85 351.92,68.96 351.92,66.75 351.54,66.37 350.27,66.37 350.14,66.5 350.14,70.31 350.52,70.69 355.09,70.69
AGND on TOP (solid shape): 355.6,44.15 355.6,38.86 355.85,38.61 357.12,38.61 357.25,38.48 357.25,37.72 357.2,37.67 354.84,37.67 354.71,37.8 354.71,42.88 354.69,42.9 354.69,43.08 353.95,43.81 352.81,43.81 351.92,42.93 351.92,40.72 351.54,40.34 350.27,40.34 350.14,40.46 350.14,44.27 350.52,44.65 355.09,44.65
AGND on BOTTOM (solid shape): 272.03,26.54 272.03,21.21 271.65,20.83 267.84,20.83 266.83,19.81 265.81,19.81 265.3,20.32 265.3,21.34 264.54,22.1 256.79,22.1 256.29,21.59 256.29,20.95 256.16,20.83 245.87,20.83 245.24,21.46 245.24,28.57 246,29.34 269.24,29.34
AGND on GND02 (solid shape): outline of 7326 points within 69.72,1.27 364.77,171.58
AGND on POWER03 (solid shape): outline of 1966 points within 5.21,2.36 86.23,102.23
GND_EARTH on TOP (solid shape): 24.07,14.92 24.07,5.78 23.37,5.08 10.92,5.08 10.16,5.84 10.16,9.53 9.02,10.67 3.3,10.67 2.92,11.05 2.92,15.49 3.43,16 22.99,16
GND_EARTH on BOTTOM (solid shape): 49.91,58.8 49.91,55.5 49.66,55.24 47.37,55.24 47.24,55.37 47.24,58.93 47.37,59.05 49.66,59.05
GND_EARTH on BOTTOM (solid shape): 51.31,79.5 51.31,77.34 51.05,77.09 47.75,77.09 47.62,77.22 47.62,79.5 47.88,79.76 51.05,79.76
GND_EARTH on BOTTOM (solid shape): 71.5,49.15 71.5,46.99 71.12,46.61 68.45,46.61 68.2,46.86 68.2,49.02 68.45,49.28 71.37,49.28
GND_EARTH on BOTTOM (solid shape): 71.5,42.16 71.5,38.86 71.37,38.73 69.34,38.73 69.22,38.86 69.22,42.16 69.34,42.29 71.37,42.29
GND_EARTH on BOTTOM (solid shape): 85.22,69.98 85.22,66.93 84.96,66.67 83.06,66.67 82.93,66.8 82.93,70.36 83.06,70.48 84.71,70.48
GND_EARTH on BOTTOM (solid shape): 3.56,64.64 3.56,17.53 6.1,14.99 22.86,14.99 22.92,14.92 24.97,14.92 26.22,14.52 27.53,14.44 27.67,14.43 28.96,13.14 28.96,10.41 28.32,9.78 28.32,1.78 27.81,1.27 9.63,1.27 8.3,8.3 1.27,9.63 1.27,64.77 3.43,64.77
GND_EARTH on GND02 (solid shape): outline of 4065 points within 1.27,1.27 92.58,83.95
P6.5V on BOTTOM (solid shape): 265.56,19.05 267.46,19.05 267.84,19.43 276.48,19.43 290.07,5.84 296.93,5.84 297.31,5.46 297.31,4.06 296.93,3.68 288.16,3.68 274.45,17.4 262.25,17.4 262.13,17.53 262.13,20.19 262.38,20.45 264.16,20.45
PGND on TOP (solid shape): 352.43,177.16 358.01,177.16 358.27,176.91 358.27,173.74 357.5,172.97 345.57,172.97 341,177.55 341,179.2 341.88,180.09 349.5,180.09
PGND on TOP (solid shape): 327.41,116.71 327.41,111.96 328.55,110.82 337.28,110.82 337.43,110.67 337.43,109.07 337.2,108.84 328.82,108.84 327.42,107.44 327.42,105.03 325.26,102.87 317.37,102.87 316.23,104.01 316.23,116.33 316.74,116.84 327.28,116.84
PGND on TOP (solid shape): 327.53,67.82 327.53,62.61 328.17,61.98 337.2,61.98 337.43,61.75 337.43,60.17 337.2,59.94 329.46,59.94 329.45,59.94 327.14,59.94 326.64,59.44 326.64,54.74 325.63,53.72 316.74,53.72 316.23,54.23 316.23,67.69 316.48,67.94 327.41,67.94
PGND on TOP (solid shape): 312.42,25.72 312.42,18.67 311.53,17.78 277.37,17.78 273.3,13.72 270.26,13.72 269.88,14.1 266.57,14.1 265.81,13.34 264.8,13.34 264.67,13.21 264.67,11.43 264.54,11.3 264.16,11.3 264.03,11.43 264.03,13.21 263.91,13.34 263.27,13.34 262.51,14.1 254.38,14.1 254.25,14.22 254.25,17.78 254.51,18.03 266.95,18.03 276.29,27.37 310.77,27.37
PGND on TOP (solid shape): outline of 406 points within 39.75,131.32 337.69,184.92
PGND on BOTTOM (solid shape): 272.42,15.24 272.42,10.92 269.88,8.38 269.88,6.73 269.49,6.35 267.33,6.35 266.7,6.99 266.7,15.24 267.21,15.75 271.91,15.75
PGND on BOTTOM (solid shape): 199.01,182.89 199.01,170.18 197.74,168.91 178.31,168.91 170.56,176.66 164.08,176.66 162.81,175.39 162.81,169.54 162.18,168.91 143.51,168.91 134.49,177.93 127.76,177.93 126.62,176.78 126.62,169.54 125.98,168.91 105.92,168.91 97.66,177.16 91.69,177.16 90.42,175.9 90.42,170.18 89.15,168.91 69.72,168.91 61.47,177.16 56.01,177.16 54.86,176.02 54.86,169.54 54.23,168.91 46.23,168.91 44.96,167.64 44.96,142.24 49.91,137.29 49.91,132.33 49.02,131.44 43.69,131.44 39.75,135.38 39.75,184.15 40.52,184.92 196.98,184.92
PGND on GND02 (solid shape): outline of 4190 points within 39.75,16.26 364.77,184.92
PGND on POWER03 (solid shape): 186.31,7.49 186.31,6.6 186.18,6.48 184.4,6.48 184.28,6.6 184.28,7.49 184.4,7.62 186.18,7.62
PGND on POWER03 (solid shape): outline of 792 points within 39.75,131.32 310.66,184.92
AC_LA on TOP (solid shape): outline of 311 points within 124.71,34.77 212.79,83.82
AC_LA on BOTTOM (solid shape): 212.22,46.74 212.22,36.2 210.95,34.92 207.9,34.92 206.88,35.94 206.88,40.13 206.25,40.77 181.99,40.77 180.97,41.78 180.97,47.12 181.61,47.75 211.2,47.75
AC_LA on POWER03 (solid shape): outline of 361 points within 127.38,34.61 212.34,82.55
AC_LA1 on BOTTOM (solid shape): 235.27,41.66 235.27,37.47 235.71,37.02 235.71,34.42 235.59,34.29 230.76,34.29 230.5,34.54 230.5,36.83 230.38,36.96 230,36.96 229.87,36.83 229.87,36.2 229.62,35.94 225.68,35.94 225.43,36.2 225.43,42.35 225.81,42.74 234.19,42.74
AC_LAB_G on TOP (solid shape): 78.99,15.75 78.99,12.83 78.23,12.06 72.77,12.06 72.64,12.19 72.64,15.49 73.03,15.88 78.87,15.88
AC_LAP on BOTTOM (solid shape): 284.99,74.3 284.99,68.58 251.08,34.67 242.44,34.67 242.32,34.8 242.32,36.58 242.19,36.7 241.81,36.7 241.68,36.58 241.68,34.42 241.55,34.29 236.6,34.29 236.47,34.42 236.47,42.42 269.37,75.31 283.97,75.31
AC_LB on TOP (solid shape): 170.94,113.28 170.94,105.92 172.97,103.89 202.69,103.89 204.47,105.66 211.07,105.66 212.47,104.27 212.47,99.19 209.8,96.52 172.12,96.52 169.99,96.98 167.83,96.69 165.67,96.98 163.54,96.52 163.32,96.52 163.14,96.34 159.86,92.49 160.43,87.46 161.29,85.97 161.29,77.6 159.51,75.82 149.61,75.82 146.43,78.99 146.43,111.63 149.1,114.3 169.93,114.3
AC_LB on BOTTOM (solid shape): 193.27,106.05 197.53,103.92 201.79,106.05 210.95,106.05 211.96,105.03 211.96,102.49 210.69,101.22 207.77,101.22 203.84,97.28 182.37,97.28 181.04,98.62 181.04,104.46 182.63,106.05
AC_LB on GND02 (solid shape): 212.5,104.81 212.5,97.92 209.84,95.25 192.91,95.25 170.43,72.77 148.72,72.77 147.57,73.91 147.57,82.42 148.46,83.31 168.02,83.31 174.75,90.04 174.75,98.04 182.82,106.11 211.2,106.11
AC_LB on POWER03 (solid shape): outline of 241 points within 147.32,76.58 212.98,114.55
AC_LB1 on TOP (solid shape): 230.76,113.16 230.76,104.65 229.62,103.5 225.04,103.5 218.69,109.86 211.44,109.86 209.71,110.09 207.97,109.86 201.04,109.86 199.39,108.2 196.22,108.2 195.45,108.97 195.45,113.16 196.72,114.43 229.49,114.43
AC_LB1 on BOTTOM (solid shape): 235.27,108.33 235.27,104.52 235.71,104.08 235.71,100.97 235.33,100.58 230.89,100.58 230.5,100.97 230.5,103 230.38,103.12 230,103.12 229.87,103 229.87,102.36 229.74,102.23 225.43,102.23 225.3,102.36 225.3,108.33 225.81,108.84 234.76,108.84
AC_LB1 on GND02 (solid shape): 230.63,116.97 230.63,104.39 229.36,103.12 219.2,103.12 214.25,108.08 196.6,108.08 195.2,109.47 195.2,117.47 196.22,118.49 229.11,118.49
AC_LB1 on POWER03 (solid shape): 231.01,113.16 231.01,105.28 229.11,103.38 223.65,103.38 219.96,107.06 197.23,107.06 196.22,108.08 196.22,113.67 197.1,114.55 229.62,114.55
AC_LBC_G on TOP (solid shape): 114.55,15.75 114.55,12.83 113.79,12.06 108.33,12.06 108.2,12.19 108.2,15.49 108.58,15.88 114.43,15.88
AC_LBP on BOTTOM (solid shape): 287.08,175.45 287.08,163.51 267.33,143.76 267.33,115.7 252.48,100.84 242.44,100.84 242.32,100.97 242.32,102.87 242.19,103 241.81,103 241.68,102.87 241.68,100.97 241.55,100.84 236.6,100.84 236.47,100.97 236.47,104.9 237.11,105.54 237.11,110.87 251.46,125.22 251.46,155.83 273.43,177.8 284.73,177.8
AC_LC on TOP (solid shape): 212.47,74.04 212.47,67.56 210.19,65.28 145.16,65.28 144.85,65.3 144.55,65.36 140.74,65.36 139.07,67.4 140.44,69.66 140.44,69.66 140.89,69.8 141.35,69.85 142.75,69.85 144.65,71.75 150.21,71.75 150.21,71.75 161.2,71.75 165.35,75.91 165.35,75.95 210.57,75.95
AC_LC on BOTTOM (solid shape): 212.22,75.31 212.22,69.22 211.07,68.07 207.52,68.07 206.25,69.34 182.37,69.34 181.1,70.61 181.1,75.56 181.86,76.33 211.2,76.33
AC_LC on GND02 (solid shape): 157.1,59.05 157.1,34.92 166.62,25.4 166.62,21.59 165.99,20.95 162.18,20.95 151.89,31.24 151.89,53.34 139.83,65.41 139.83,68.2 141.1,69.47 146.69,69.47
AC_LC on POWER03 (solid shape): 212.34,75.82 212.34,64.14 210.69,62.48 139.83,62.48 139.06,63.25 139.06,72.77 140.08,73.79 177.67,73.79 180.97,77.09 211.07,77.09
AC_LC1 on BOTTOM (solid shape): 235.33,75.69 235.33,70.99 235.71,70.61 235.71,67.94 235.46,67.69 230.76,67.69 230.5,67.94 230.5,69.98 230.38,70.1 230,70.1 229.87,69.98 229.87,69.47 229.74,69.34 225.55,69.34 225.04,69.85 225.04,73.37 225.06,73.39 225.06,75.71 225.68,76.33 234.7,76.33
AC_LCA_G on TOP (solid shape): 150.11,15.75 150.11,12.83 149.35,12.06 143.89,12.06 143.76,12.19 143.76,15.49 144.15,15.88 149.99,15.88
AC_LCP on BOTTOM (solid shape): 287.65,123.57 287.65,103.38 251.97,67.69 242.7,67.69 242.32,68.07 242.32,69.98 242.19,70.1 241.81,70.1 241.68,69.98 241.68,68.07 241.3,67.69 236.73,67.69 236.47,67.94 236.47,77.85 272.54,113.92 272.54,124.84 273.81,126.11 285.12,126.11
DC_14V_INPUT on BOTTOM (solid shape): outline of 191 points within 305.69,3.81 337.57,12.06
GGND on BOTTOM (solid shape): 361.7,82.8 361.7,81.66 360.68,80.64 360.68,78.36 360.93,78.11 360.93,74.42 360.68,74.17 358.27,74.17 358.01,74.42 358.01,82.8 358.14,82.93 361.57,82.93
GGND on BOTTOM (solid shape): 361.7,157.73 361.7,156.46 360.55,155.32 360.55,153.54 360.93,153.16 360.93,149.35 360.68,149.1 358.27,149.1 358.01,149.35 358.01,157.73 358.14,157.86 361.57,157.86
GGND on BOTTOM (solid shape): 361.7,131.7 361.7,130.43 360.55,129.29 360.55,127.51 360.93,127.13 360.93,123.32 360.68,123.06 358.27,123.06 358.01,123.32 358.01,131.7 358.14,131.83 361.57,131.83
GGND on BOTTOM (solid shape): 361.7,108.84 361.7,107.57 360.55,106.43 360.55,104.39 360.93,104.01 360.93,100.46 360.68,100.2 358.27,100.2 358.01,100.46 358.01,108.84 358.14,108.97 361.57,108.97
GGND on BOTTOM (solid shape): 361.7,59.94 361.7,58.67 360.55,57.53 360.55,55.63 360.93,55.24 360.93,51.56 360.68,51.31 358.27,51.31 358.01,51.56 358.01,59.94 358.14,60.07 361.57,60.07
GGND on BOTTOM (solid shape): 361.7,33.91 361.7,32.64 360.55,31.5 360.55,29.72 360.93,29.34 360.93,25.53 360.68,25.27 358.27,25.27 358.01,25.53 358.01,33.91 358.14,34.04 361.57,34.04
GGND on GND02 (solid shape): outline of 1037 points within 358.39,25.91 364.77,163.32
GGND on POWER03 (solid shape): outline of 1062 points within 358.39,24.89 364.77,161.8
IGND on POWER03 (solid shape): outline of 85 points within 305.44,4.32 333.12,12.06
LA on TOP (solid shape): 18.28,67.95 18.29,67.95 20.1,66.14 20.1,65.65 20.09,65.64 20.09,65.04 18.8,63.75 18.8,60.33 18.8,60.33 18.8,59.85 19.45,59.19 19.75,58.78 20.1,58.41 20.1,57.15 19.08,56.13 6.99,56.13 6.35,56.77 6.35,68.96 7.05,69.66 16.57,69.66
LA on BOTTOM (solid shape): 18.87,69.66 19.12,67.44 20.51,65.7 20.51,64.68 18.82,61.38 20.51,58.08 20.51,56.71 19.94,56.13 7.37,56.13 6.6,56.9 6.6,68.9 7.37,69.66
LB on TOP (solid shape): 18.75,51.88 18.83,51.85 18.85,51.77 19.15,49.61 20.51,47.92 20.51,46.9 18.82,43.83 20.15,40.59 20.15,39.12 19.38,38.35 6.99,38.35 6.35,38.99 6.35,51.18 7.05,51.88
LB on BOTTOM (solid shape): 18.87,51.88 19.12,49.66 20.51,47.92 20.51,46.9 18.83,43.97 19.95,40.78 19.95,38.86 19.44,38.35 7.37,38.35 6.6,39.12 6.6,50.99 7.49,51.88
LC on TOP (solid shape): 18.54,33.32 18.54,31.77 19.67,30.85 20.05,30.06 19.67,29.27 18.54,28.36 18.54,24.14 19.98,22.7 19.98,20.95 19.6,20.57 6.99,20.57 6.35,21.21 6.35,33.4 7.05,34.1 17.76,34.1
LC on BOTTOM (solid shape): 18.82,33.27 19.3,31.51 20.51,30.14 20.51,29.12 18.82,25.82 20.51,22.52 20.51,21.15 19.94,20.57 7.24,20.57 6.6,21.21 6.6,33.59 7.11,34.1 17.99,34.1
PFC_G_HA on BOTTOM (solid shape): 353.31,35.18 353.31,33.91 353.19,33.78 351.41,33.78 351.15,33.53 351.15,30.61 351.41,30.35 351.41,25.78 351.15,25.53 349.38,25.53 349,25.91 349,30.3 349.25,30.56 349.25,35.18 349.38,35.31 353.19,35.31
PFC_G_HB on BOTTOM (solid shape): 353.31,132.97 353.31,131.7 353.19,131.57 351.41,131.57 351.15,131.32 351.15,128.4 351.41,128.14 351.41,123.57 351.15,123.32 349.38,123.32 349,123.7 349,128.09 349.25,128.35 349.25,132.97 349.38,133.1 353.19,133.1
PFC_G_HC on BOTTOM (solid shape): 353.31,84.07 353.31,82.8 353.19,82.68 351.41,82.68 351.15,82.42 351.15,79.5 351.41,79.25 351.41,74.68 351.15,74.42 349.38,74.42 349,74.8 349,79.2 349.25,79.45 349.25,84.07 349.38,84.2 353.19,84.2
PFC_G_LA on BOTTOM (solid shape): 353.31,61.21 353.31,59.94 353.19,59.82 351.41,59.82 351.15,59.56 351.15,56.64 351.41,56.39 351.41,51.82 351.15,51.56 349.38,51.56 349,51.94 349,56.34 349.25,56.59 349.25,61.21 349.38,61.34 353.19,61.34
